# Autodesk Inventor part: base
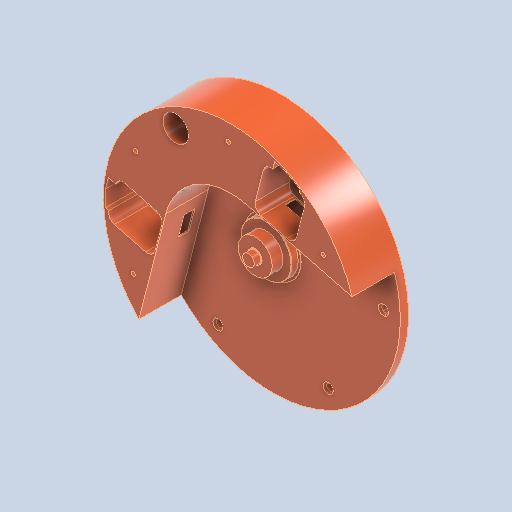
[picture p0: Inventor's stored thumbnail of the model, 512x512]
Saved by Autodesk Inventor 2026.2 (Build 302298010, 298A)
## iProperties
Created: 2025-06
Part Number: base
Material: Plastique ABS
Document SubType Name: Modeling
Designer: mel
Density: 1.06 g/cm^3
Appearance: Lisse - Orange clair
Mass: 1963.82 g
Surface Area: 503.372 cm^2
Volume: 250.168 cm^3
Author: mel
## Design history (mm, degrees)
feature "Base - Nema 17"
sketch "Esquisse1"
  geometry: C1 r 14.5 at (16.586, -20.5) reference; 1 further point
extrude "Extrusion1" join sketch "Esquisse1" stored distance "d0" = 10; taper "d1" = 0 deg
sketch "Esquisse2"
  geometry: C1 r 14.75 at (0, 0) reference; 1 further point
extrude "Extrusion2" join sketch "Esquisse2" stored distance "d2" = 10; taper "d3" = 0 deg
sketch "Esquisse3"
  geometry: L1 (-3.768, 37.439)-(-0.354, 40.854) reference; L2 (-3.914, 3.914)-(-3.914, 37.086) reference; L3 (-0.354, 0.146)-(-3.768, 3.561) reference; L4 (33.172, 0)-(0, 0) reference; L5 (36.939, 3.561)-(33.525, 0.146) reference; L6 (37.086, 37.086)-(37.086, 3.914) reference; L7 (33.525, 40.854)-(36.939, 37.439) reference; L8 (0, 41)-(33.172, 41) reference; C1 r 3.25 at (1.086, 5) reference; C2 r 3.25 at (1.086, 36) reference; C3 r 3.25 at (32.086, 5) reference; C4 r 16.5 at (16.586, 20.5) reference; C5 r 3.25 at (32.086, 36) reference; A1 r 0.5 centre (-3.414, 37.086) between (-3.768, 37.439) and (-3.914, 37.086) reference; A2 r 0.5 centre (-3.414, 3.914) between (-3.914, 3.914) and (-3.768, 3.561) reference; A3 r 0.5 centre (0, 0.5) between (-0.354, 0.146) and (0, 0) reference; A4 r 0.5 centre (33.172, 0.5) between (33.172, 0) and (33.525, 0.146) reference; A5 r 0.5 centre (36.586, 3.914) between (36.939, 3.561) and (37.086, 3.914) reference; A6 r 0.5 centre (36.586, 37.086) between (37.086, 37.086) and (36.939, 37.439) reference; A7 r 0.5 centre (33.172, 40.5) between (33.525, 40.854) and (33.172, 41) reference; A8 r 0.5 centre (0, 40.5) between (0, 41) and (-0.354, 40.854) reference; 1 further point
extrude "Extrusion3" join sketch "Esquisse3" stored distance "d4" = 10; taper "d5" = 0 deg
sketch "Esquisse4"
  geometry: C1 r 16.5 at (16.586, -20.5) reference; C2 r 75 at (16.586, -20.5); 1 further point
  constraints: 1 centre point, 1 coincident
  dimensions: "d6" = 150 diameter of C2
extrude "Extrusion4" join sketch "Esquisse4" stored distance "d7" = 10; taper "d8" = 0 deg
sketch "Esquisse5"
  geometry: C1 r 14.75 at (0, 0) reference; 2 further points
  dimensions: "d9" = 65 distance of point (65, -0.034) C1.centre
hole "Perçage1" sketch "Esquisse5" at (65, -0.034) diameter "d10" = 4; stored, may be unused: countersink angle "d14" = 90 deg, drill point angle "d16" = 118 deg; dims "d11" = 8, "d12" = 6, "d13" = 2, "d15" = 8
pattern_circular "Réseau circulaire1" dims angle "d18" = 360 deg
sketch "Esquisse6"
  geometry: L1 (-36.324, 9.317)-(-83.324, -173.924) reference; L2 (9.814, 38.261)-(71.57, 22.421); L3 (-85.261, -173.427)-(-38.261, 9.814); A1 r 37.5 centre (0, 0) between (35.488, -12.119) and (-36.324, 9.317) reference; A2 r 39.5 centre (0, 0) between (9.814, 38.261) and (-38.261, 9.814); 3 further points
  constraints: 4 end point, 2 point on circle, 1 centre point, 2 other
  dimensions: "d22" = 2 distance between parallel lines of L1 L3
extrude "Extrusion5" join sketch "Esquisse6" distance "d23" = 25; taper "d24" = 0 deg
sketch "Esquisse7"
  geometry: C1 r 10 at (0, 0); 1 further point
  constraints: 1 centre point
  dimensions: "d25" = 20 diameter of C1
node "Plan de construction1"
extrude "Extrusion6" join sketch "Esquisse7" stored distance "d26" = 10; taper "d27" = 0 deg
sketch "Esquisse8"
  geometry: C1 r 3.475 at (0, 0); C2 r 10 at (0, 0) reference; 1 further point
  constraints: 1 centre point
  dimensions: "d28" = 6.95 diameter of C1
extrude "Extrusion7" cut sketch "Esquisse8" distance "d29" = 3.75; taper "d30" = 0 deg
sketch "Esquisse9"
  geometry: C1 r 3.475 at (0, 0) reference; C2 r 4 at (0, 0); C3 r 12.5 at (0, 0) reference; C4 r 15.82 at (0, 0) reference; 1 further point
  constraints: 1 centre point, 1 coincident
  dimensions: "d31" = 8 diameter of C2
extrude "Extrusion8" cut sketch "Esquisse9" distance "d32" = 0.25; taper "d33" = 0 deg
sketch "Esquisse10"
  geometry: C1 r 2 at (32.529, 56.275) reference; C2 r 2 at (-32.471, 56.308) reference; C3 r 2 at (-65, 0.034) reference; C4 r 7.5 at (-65, 0.034); C5 r 7.5 at (-32.471, 56.308); C6 r 7.5 at (32.529, 56.275); 1 further point
  constraints: 3 centre point, 3 coincident
  dimensions: "d34" = 15 diameter of C4; "d35" = 15 diameter of C5; "d36" = 15 diameter of C6
extrude "Extrusion9" cut sketch "Esquisse10" stored distance "d37" = 10; taper "d38" = 0 deg
sketch "Esquisse11"
  geometry: L1 (-46.64, -11.782)-(-46.329, -10.571) reference; L2 (-46.329, -10.571)-(-50.204, -9.577) reference; L3 (-50.204, -9.577)-(-46.85, 3.5) reference; L4 (-46.85, 3.5)-(-42.975, 2.506) reference; L5 (-42.975, 2.506)-(-42.664, 3.717) reference; L6 (-44.465, 6.759)-(-62.869, 11.48) reference; L7 (-65.912, 9.679)-(-69.887, -5.819) reference; L8 (-68.087, -8.862)-(-49.682, -13.582) reference; L9 (-62.621, 3.752)-(-62.342, 3.681) reference; L10 (-62.342, 3.681)-(-62.653, 2.47) reference; L11 (-62.653, 2.47)-(-62.929, 2.541) reference; L12 (-61.313, 2.214)-(-61.263, 2.408) reference; L13 (-61.263, 2.408)-(-61.249, 2.405) reference; L14 (-60.909, 3.148)-(-60.99, 2.835) reference; L15 (-60.99, 2.835)-(-60.709, 2.763) reference; L16 (-60.709, 2.763)-(-60.745, 2.622) reference; L17 (-60.745, 2.622)-(-61.185, 2.734) reference; L18 (-61.185, 2.734)-(-61.049, 3.263) reference; L19 (-62.874, 0.031)-(-62.824, 0.226) reference; L20 (-62.824, 0.226)-(-62.811, 0.222) reference; L21 (-62.642, 0.884)-(-62.654, 0.887) reference; L22 (-62.654, 0.887)-(-62.605, 1.079) reference; L23 (-64.188, -2.146)-(-63.782, -2.25) reference; L24 (-63.782, -2.25)-(-63.819, -2.393) reference; L25 (-63.819, -2.393)-(-64.792, -2.143) reference; L26 (-64.792, -2.143)-(-64.755, -2) reference; L27 (-64.755, -2)-(-64.349, -2.104) reference; L28 (-64.349, -2.104)-(-64.075, -1.037) reference; L29 (-64.075, -1.037)-(-63.914, -1.078) reference; L30 (-63.914, -1.078)-(-64.188, -2.146) reference; L31 (-59.367, 9.033)-(-58.759, 9.393) reference; L32 (-58.759, 9.393)-(-51.494, 7.53) reference; L33 (-51.494, 7.53)-(-51.991, 5.592) reference; L34 (-51.991, 5.592)-(-52.599, 5.232) reference; L35 (-52.599, 5.232)-(-59.864, 7.096) reference; L36 (-59.864, 7.096)-(-59.367, 9.033) reference; L37 (-62.642, -1.89)-(-62.835, -2.645) reference; L38 (-62.835, -2.645)-(-62.996, -2.604) reference; L39 (-62.996, -2.604)-(-62.803, -1.848) reference; L40 (-63.356, -1.702)-(-63.551, -2.462) reference; L41 (-63.551, -2.462)-(-63.712, -2.42) reference; L42 (-63.712, -2.42)-(-63.518, -1.665) reference; L43 (-61.201, 0.807)-(-61.028, 0.762) reference; L44 (-61.028, 0.762)-(-60.921, -0.555) reference; L45 (-60.921, -0.555)-(-61.094, -0.511) reference; L46 (-61.094, -0.511)-(-61.171, 0.581) reference; L47 (-61.171, 0.581)-(-61.765, -0.339) reference; L48 (-61.765, -0.339)-(-61.929, -0.297) reference; L49 (-61.929, -0.297)-(-61.201, 0.807) reference; L50 (-63.874, 0.288)-(-63.824, 0.482) reference; L51 (-63.824, 0.482)-(-63.811, 0.479) reference; L52 (-63.642, 1.14)-(-63.654, 1.143) reference; L53 (-63.654, 1.143)-(-63.605, 1.336) reference; L54 (-61.917, 3.571)-(-61.649, 2.39) reference; L55 (-61.649, 2.39)-(-61.381, 3.434) reference; L56 (-61.381, 3.434)-(-61.231, 3.396) reference; L57 (-61.231, 3.396)-(-61.541, 2.185) reference; L58 (-61.541, 2.185)-(-61.77, 2.243) reference; L59 (-61.77, 2.243)-(-62.012, 3.327) reference; L60 (-62.012, 3.327)-(-62.258, 2.368) reference; L61 (-62.258, 2.368)-(-62.408, 2.407) reference; L62 (-62.408, 2.407)-(-62.097, 3.618) reference; L63 (-62.097, 3.618)-(-61.917, 3.571) reference; L64 (33.744, 34.962)-(32.534, 35.273) reference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; C1 r 0.5 at (-49.097, 2.786) reference; C2 r 0.5 at (-51.83, -7.869) reference; C3 r 0.5 at (-50.464, -2.542) reference; C4 r 0.5 at (-66.593, -1.027) reference; C5 r 1.5 at (-63.13, 8.45) reference; C6 r 1.5 at (-66.857, -6.08) reference; C7 r 0.5 at (-65.331, 3.894) reference; C8 r 0.5 at (-65.962, 1.433) reference; C9 r 0.5 at (22.158, 44.128) reference; C10 r 0.5 at (32.814, 41.395) reference; C11 r 0.5 at (27.486, 42.762) reference; C12 r 1.5 at (23.948, 59.155) reference; C13 r 1.5 at (38.478, 55.428) reference; A1 r 2.5 centre (-45.086, 4.338) between (-42.664, 3.717) and (-44.465, 6.759) reference; A2 r 2.5 centre (-63.49, 9.058) between (-62.869, 11.48) and (-65.912, 9.679) reference; A3 r 2.5 centre (-67.465, -6.44) between (-69.887, -5.819) and (-68.087, -8.862) reference; A4 r 2.5 centre (-49.061, -11.161) between (-49.682, -13.582) and (-46.64, -11.782) reference; A5 r 2.5 centre (34.366, 37.384) between (33.744, 34.962) and (36.787, 36.763) reference; A6 r 2.5 centre (39.086, 55.788) between (41.508, 55.167) and (39.707, 58.21) reference; A7 r 2.5 centre (23.588, 59.763) between (24.209, 62.185) and (21.166, 60.385) reference; A8 r 2.5 centre (18.867, 41.359) between (16.446, 41.98) and (18.246, 38.938) reference; A9 r 0.5 centre (33.922, 57.629) between (34.312, 57.942) and (33.73, 58.091) reference; A10 r 0.5 centre (29.001, 58.891) between (29.391, 59.204) and (28.81, 59.353) reference; A11 r 0.5 centre (31.461, 58.26) between (31.851, 58.573) and (31.27, 58.722) reference; A12 r 4.5 centre (-63.49, 9.058) between (-62.372, 13.417) and (-67.849, 10.176); A13 r 4.5 centre (-45.086, 4.338) between (-40.727, 3.22) and (-43.968, 8.697); A14 r 4.5 centre (-49.061, -11.161) between (-50.179, -15.52) and (-44.702, -12.279); A15 r 4.5 centre (-67.465, -6.44) between (-71.824, -5.322) and (-68.583, -10.799); A16 r 4.5 centre (34.366, 37.384) between (33.248, 33.025) and (38.725, 36.266); A17 r 4.5 centre (18.867, 41.359) between (14.508, 42.477) and (17.749, 37); A18 r 4.5 centre (23.588, 59.763) between (24.706, 64.122) and (19.229, 60.882); A19 r 4.5 centre (39.086, 55.788) between (43.445, 54.67) and (40.204, 60.147); A20 r 75 centre (0, 0) between (71.57, 22.421) and (-54.102, -51.943) reference; A21 r 74 centre (0, 0) between (40.639, 61.842) and (31.867, 66.787); A22 r 74 centre (0, 0) between (-73.854, 4.64) and (-73.844, -4.804); 58 further points
  constraints: 36 end point, 22 point on circle, 10 centre point, 4 parallel, 2 point on line, 11 other
  dimensions: "d40" = 2 distance between parallel lines of L65 L79
extrude "Extrusion10" cut sketch "Esquisse11" distance "d41" = 20; taper "d42" = 0 deg
sketch "Esquisse12"
  geometry: L1 (13.275, -21.5)-(13.275, -8.5) reference; L2 (19.025, -21.5)-(19.025, -8.5) reference; L3 (13.275, -21.5)-(19.025, -21.5) reference; L4 (13.275, -8.5)-(19.025, -8.5) reference; L5 (13.025, -8.25)-(13.025, -21.75); L6 (13.025, -21.75)-(19.275, -21.75); L7 (19.275, -21.75)-(19.275, -8.25); L8 (19.275, -8.25)-(13.025, -8.25); 1 further point
  constraints: 8 end point, 3 other
  dimensions: "d44" = 0.25 distance between parallel lines of L1 L5
extrude "Extrusion11" cut sketch "Esquisse12" stored distance "d45" = 20; taper "d46" = 0 deg
sketch "Esquisse13"
  geometry: L1 (-41.255, 11.625)-(-54.255, 11.625) reference; L2 (-54.255, 5.875)-(-54.255, 11.625) reference; L3 (-41.255, 5.875)-(-41.255, 11.625) reference; L4 (-41.255, 5.875)-(-54.255, 5.875) reference; L5 (-54.505, 11.875)-(-41.005, 11.875); L6 (-41.005, 11.875)-(-41.005, 5.625); L7 (-41.005, 5.625)-(-54.505, 5.625); L8 (-54.505, 5.625)-(-54.505, 11.875); 1 further point
  constraints: 8 end point, 3 other
  dimensions: "d47" = 0.25 distance between parallel lines of L1 L5
extrude "Extrusion12" cut sketch "Esquisse13" stored distance "d48" = 0.25 (= d47); taper "d49" = 0 deg
sketch "Esquisse14"
  geometry: C1 r 1.5 at (-66.857, -6.08) reference; C2 r 1.5 at (-63.13, 8.45) reference; C3 r 1.5 at (23.948, 59.155) reference; C4 r 1.5 at (38.478, 55.428) reference; 1 further point
hole "Perçage2" sketch "Esquisse14" at (-66.857, -6.08), (-63.13, 8.45), (23.948, 59.155), (38.478, 55.428) diameter "d50" = 2.5; stored, may be unused: countersink angle "d54" = 90 deg, drill point angle "d56" = 118 deg; dims "d51" = 6, "d52" = 4, "d53" = 2, "d55" = 12
sketch "Esquisse15"
  geometry: C1 r 1.25 at (-57.455, -30.396) reference; C2 r 2 at (-56.033, 32.944) reference; C3 r 2 at (-1.377, 64.985) reference; C4 r 2 at (54.588, 35.287) reference; 1 further point
hole "Perçage3" sketch "Esquisse15" at (-57.455, -30.396), (-56.033, 32.944), (-1.377, 64.985), (54.588, 35.287) diameter "d57" = 2.5; stored, may be unused: countersink angle "d61" = 90 deg, drill point angle "d63" = 118 deg; dims "d58" = 6, "d59" = 4, "d60" = 2, "d62" = 12
node "Solide1"
node "Boucle projetée1"
node "Référence1"
node "Référence2"
node "Référence3"
node "Référence4"
node "Référence5"
node "Référence6"
node "Référence7"
node "Référence8"
node "Référence9"
node "Référence10"
node "Référence11"
node "Référence12"
node "Référence13"
node "Référence14"
node "Référence15"
node "Référence16"
node "Référence17"
node "Référence18"
node "Référence19"
node "Référence20"
node "Référence21"
node "Référence22"
node "Référence23"
node "Référence24"
node "Référence25"
node "Référence26"
node "Référence27"
node "Référence28"
node "Référence29"
node "Référence30"
node "Référence31"
node "Référence32"
node "Référence33"
other parameters: "d39" = 2, "d43" = 1
